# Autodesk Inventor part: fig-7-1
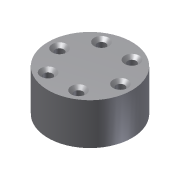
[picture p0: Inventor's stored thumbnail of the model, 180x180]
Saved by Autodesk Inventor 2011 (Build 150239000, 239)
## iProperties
Created: 2004-05
Part Number: fig-7-1
Document SubType Name: Modeling
Designer: CADCIM Technologies
Manufacturer: Standard
Standards Organization: Custom
Density: 1 g/cm^3
Author: CADCIM Technologies
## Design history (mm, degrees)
sketch "Sketch1"
  geometry: C1 r 17.175 at (0, 0)
  constraints: 1 centre point
extrude "Extrusion1" new body sketch "Sketch1" distance "d0" = 17; taper "d1" = 0 deg
sketch "Sketch2"
  geometry: 1 further point
hole "Hole1" sketch "Sketch2" at (12.571, -0.074) diameter "d2" = 3.5; stored, may be unused: countersink angle "d6" = 90 deg, drill point angle "d8" = 118 deg; dims "d3" = 6, "d4" = 6, "d5" = 2, "d7" = 8
pattern_circular "Circular Pattern1" dims angle "d11" = 360 deg
body "Solid1"
